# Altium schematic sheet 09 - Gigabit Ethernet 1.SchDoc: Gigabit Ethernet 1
size A3; PageSetup: Record=PageOptions¦CenterHorizontal=True¦CenterVertical=True¦PrintScale=0.70¦XCorrection=1.00¦YCorrection=1.00¦PrintKind=0¦BorderSize=5000000¦LeftOffset=0¦BottomOffset=0¦Orientation=2¦PaperLength=4200¦PaperWidth=2970¦Scale=100¦PaperSource=7¦PrintQuality=600¦MediaType=1¦DitherType=10¦PaperKind=A4¦PrintScaleMode=1; Author: Juan Anzola; SheetNumber: 9; SheetTotal: 20
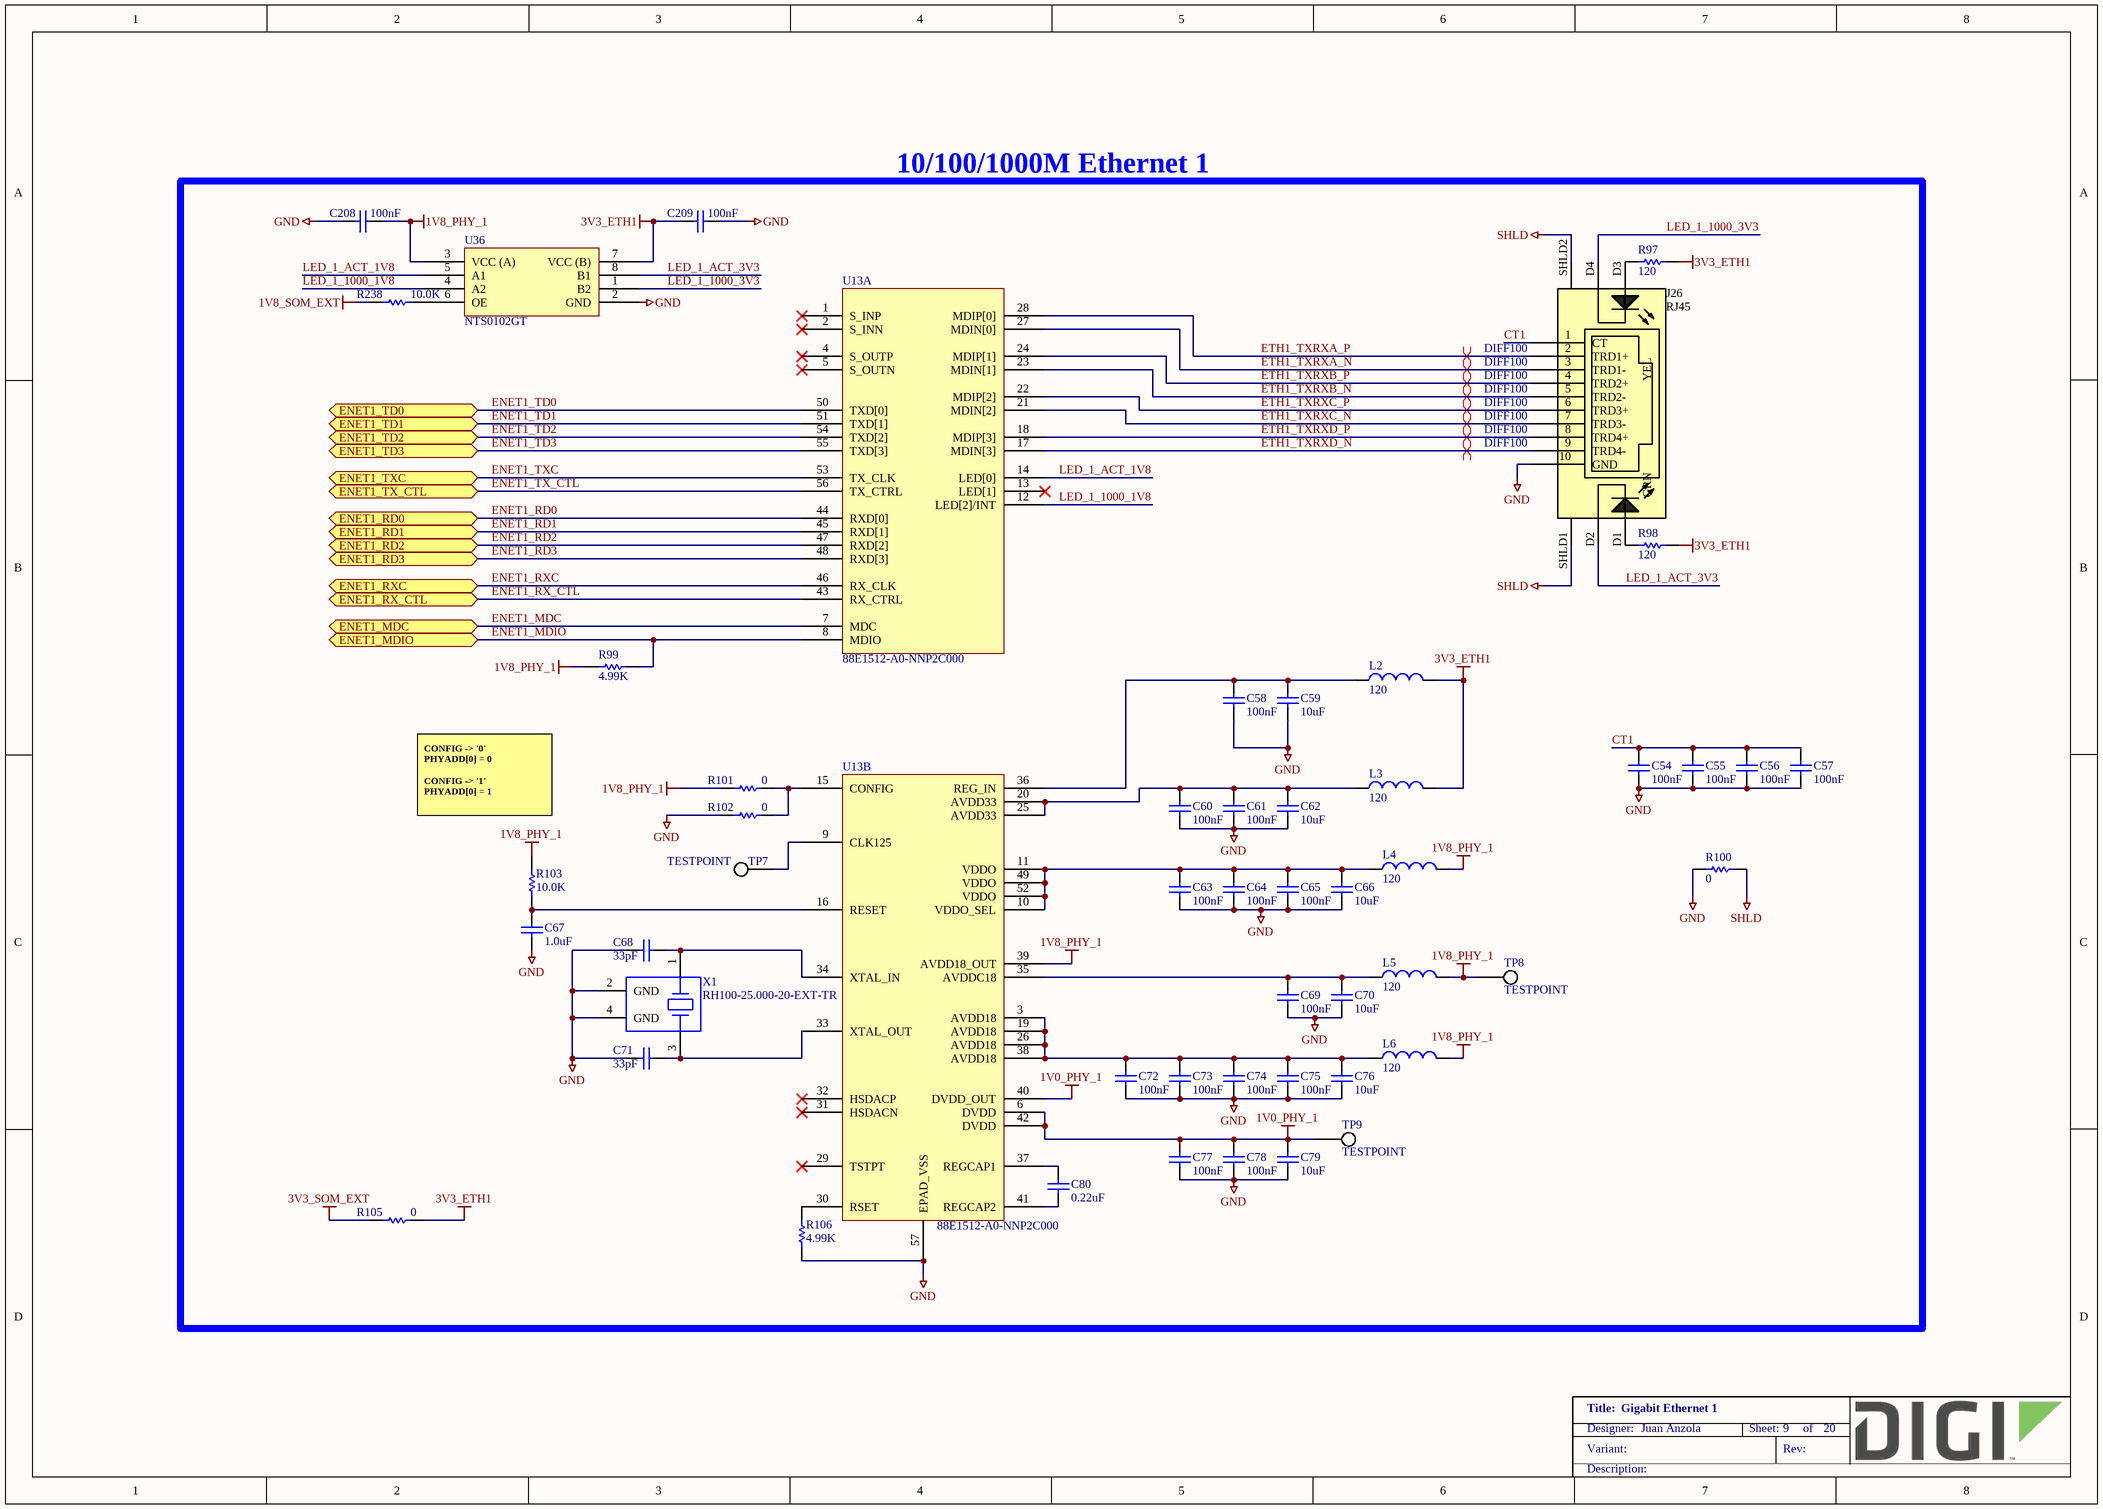
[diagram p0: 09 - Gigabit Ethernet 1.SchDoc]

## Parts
C54  100nF  [CAPC1005X55N]
C55  100nF  [CAPC1005X55N]
C56  100nF  [CAPC1005X55N]
C57  100nF  [CAPC1005X55N]
C58  100nF  [CAPC1005X55N]
C59  10uF  [CAPC2013X135N]
C60  100nF  [CAPC1005X55N]
C61  100nF  [CAPC1005X55N]
C62  10uF  [CAPC2013X135N]
C63  100nF  [CAPC1005X55N]
C64  100nF  [CAPC1005X55N]
C65  100nF  [CAPC1005X55N]
C66  10uF  [CAPC2013X135N]
C67  1.0uF  [CAPC1005X55N]
C68  33pF  [CAPC1005X55N]
C69  100nF  [CAPC1005X55N]
C70  10uF  [CAPC2013X135N]
C71  33pF  [CAPC1005X55N]
C72  100nF  [CAPC1005X55N]
C73  100nF  [CAPC1005X55N]
C74  100nF  [CAPC1005X55N]
C75  100nF  [CAPC1005X55N]
C76  10uF  [CAPC2013X135N]
C77  100nF  [CAPC1005X55N]
C78  100nF  [CAPC1005X55N]
C79  10uF  [CAPC2013X135N]
C80  0.22uF  [CAPC1005X55N]
C208  100nF  [CAPC1005X55N]
C209  100nF  [CAPC1005X55N]
J26  RJ45  [XMULTIPLE_XMG-J1B211]
L2  120  [INDC1005X60N]
L3  120  [INDC1005X60N]
L4  120  [INDC1005X60N]
L5  120  [INDC1005X60N]
L6  120  [INDC1005X60N]
R97  120  [RESC1005X40N]
R98  120  [RESC1005X40N]
R99  4.99K  [RESC1005X40N]
R100  0  [RESC3225X60N]
R101  0  [RESC1609X55N]
R102  0  [RESC1609X55N]
R103  10.0K  [RESC1005X40N]
R105  0  [RESC1609X55N]
R106  4.99K  [RESC1005X40N]
R238  10.0K  [RESC1005X40N]
TP7  TESTPOINT  [TP0762]  (no BOM)
TP8  TESTPOINT  [TP0762]  (no BOM)
TP9  TESTPOINT  [TP0762]  (no BOM)
U13  88E1512-A0-NNP2C000  [QFN56P8mmx8mm-4.50mmPAD]  (parts A,B of 2)
U36  NTS0102GT  [PSON50P195X100X50-8N]
X1  RH100-25.000-20-EXT-TR  [OSC210P320X250X90-4N]

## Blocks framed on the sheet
10/100/1000M Ethernet 1: C54-C80 C208 C209 J26 L2-L6 R97-R103 R105 R106 R238 TP7-TP9 U13 U36 X1

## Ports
ENET1_MDC (bidir), ENET1_MDIO (bidir), ENET1_RD0 (bidir), ENET1_RD1 (bidir), ENET1_RD2 (bidir), ENET1_RD3 (bidir), ENET1_RX_CTL (bidir), ENET1_RXC (bidir), ENET1_TD0 (bidir), ENET1_TD1 (bidir), ENET1_TD2 (bidir), ENET1_TD3 (bidir), ENET1_TX_CTL (bidir), ENET1_TXC (bidir)

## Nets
1V0_PHY_1: C77.2 C78.2 C79.2 TP9.1 U13.6(DVDD) U13.40(DVDD_OUT) U13.42(DVDD)
1V8_PHY_1: C208.2 L4.2 L5.2 L6.2 R99.1 R101.1 R103.2 TP8.1 U13.39(AVDD18_OUT) U36.3(VCC_(A))
1V8_SOM_EXT: R238.1
3V3_ETH1: C209.1 L2.2 L3.2 R97.1 R98.1 R105.2 U36.7(VCC_(B))
3V3_SOM_EXT: R105.1
GND: C54.1 C55.1 C56.1 C57.1 C58.1 C59.1 C60.1 C61.1 C62.1 C63.1 C64.1 C65.1 C66.1 C67.2 C68.1 C69.1 C70.1 C71.1 C72.1 C73.1 C74.1 C75.1 C76.1 C77.1 C78.1 C79.1 C208.1 C209.2 J26.10(GND) R100.1 R102.1 R106.1 U13.57(EPAD_VSS) U36.2(GND) X1.2(GND) X1.4(GND)
SHLD: J26.SHLD1(SHLD) J26.SHLD2(SHLD) R100.2
CT1: C54.2 C55.2 C56.2 C57.2 J26.1(CT)
ENET1_MDC: U13.7(MDC) ; port ENET1_MDC
ENET1_MDIO: R99.2 U13.8(MDIO) ; port ENET1_MDIO
ENET1_RD0: U13.44(RXD[0]) ; port ENET1_RD0
ENET1_RD1: U13.45(RXD[1]) ; port ENET1_RD1
ENET1_RD2: U13.47(RXD[2]) ; port ENET1_RD2
ENET1_RD3: U13.48(RXD[3]) ; port ENET1_RD3
ENET1_RX_CTL: U13.43(RX_CTRL) ; port ENET1_RX_CTL
ENET1_RXC: U13.46(RX_CLK) ; port ENET1_RXC
ENET1_TD0: U13.50(TXD[0]) ; port ENET1_TD0
ENET1_TD1: U13.51(TXD[1]) ; port ENET1_TD1
ENET1_TD2: U13.54(TXD[2]) ; port ENET1_TD2
ENET1_TD3: U13.55(TXD[3]) ; port ENET1_TD3
ENET1_TX_CTL: U13.56(TX_CTRL) ; port ENET1_TX_CTL
ENET1_TXC: U13.53(TX_CLK) ; port ENET1_TXC
ETH1_TXRXA_N: J26.3(TRD1-) U13.27(MDIN[0])
ETH1_TXRXA_P: J26.2(TRD1+) U13.28(MDIP[0])
ETH1_TXRXB_N: J26.5(TRD2-) U13.23(MDIN[1])
ETH1_TXRXB_P: J26.4(TRD2+) U13.24(MDIP[1])
ETH1_TXRXC_N: J26.7(TRD3-) U13.21(MDIN[2])
ETH1_TXRXC_P: J26.6(TRD3+) U13.22(MDIP[2])
ETH1_TXRXD_N: J26.9(TRD4-) U13.17(MDIN[3])
ETH1_TXRXD_P: J26.8(TRD4+) U13.18(MDIP[3])
LED_1_1000_1V8: U13.12(LED[2]/INT) U36.4(A2)
LED_1_1000_3V3: J26.D4 U36.1(B2)
LED_1_ACT_1V8: U13.14(LED[0]) U36.5(A1)
LED_1_ACT_3V3: J26.D2 U36.8(B1)
NetC58_2: C58.2 C59.2 L2.1 U13.36(REG_IN)
NetC60_2: C60.2 C61.2 C62.2 L3.1 U13.20(AVDD33) U13.25(AVDD33)
NetC63_2: C63.2 C64.2 C65.2 C66.2 L4.1 U13.10(VDDO_SEL) U13.11(VDDO) U13.49(VDDO) U13.52(VDDO)
NetC67_1: C67.1 R103.1 U13.16(RESET)
NetC68_2: C68.2 U13.34(XTAL_IN) X1.1
NetC69_2: C69.2 C70.2 L5.1 U13.35(AVDDC18)
NetC71_2: C71.2 U13.33(XTAL_OUT) X1.3
NetC72_2: C72.2 C73.2 C74.2 C75.2 C76.2 L6.1 U13.3(AVDD18) U13.19(AVDD18) U13.26(AVDD18) U13.38(AVDD18)
NetC80_1: C80.1 U13.37(REGCAP1)
NetC80_2: C80.2 U13.41(REGCAP2)
NetJ26_D1: J26.D1 R98.2
NetJ26_D3: J26.D3 R97.2
NetR101_2: R101.2 R102.2 U13.15(CONFIG)
NetR106_2: R106.2 U13.30(RSET)
NetR238_2: R238.2 U36.6(OE)
NetTP7_1: TP7.1 U13.9(CLK125)

Not connected (* = marked no-connect by the designer): U13 1(S_INP)* 2(S_INN)* 4(S_OUTP)* 5(S_OUTN)* 13(LED[1])* 29(TSTPT)* 31(HSDACN)* 32(HSDACP)*

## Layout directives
differential pair; differential pair class DIFF100: ETH1_TXRXA_N, ETH1_TXRXA_P, ETH1_TXRXC_N, ETH1_TXRXC_P, ETH1_TXRXD_N, ETH1_TXRXD_P
differential pair; net class DIFF100; differential pair class DIFF100: ETH1_TXRXB_N, ETH1_TXRXB_P

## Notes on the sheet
- CONFIG -> '0'
  PHYADD[0] = 0
  CONFIG -> '1'
  PHYADD[0] = 1

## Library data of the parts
C54 C56 C57 = 1000006: CAP 100nF 16V 10% X7R 0402; Part_Type: Capacitor; Manufacturer: Murata; Manufacturer_Part_Number: GRM155R71C104KA88D; Digi_PN: 14050552; Component_Life_Cycle_State: CAD Reviewed; Area: 0,95; Project: KITT; Tolerance: 10
C55 C58 C65 C72 C75 C77 C208 C209 = 1000006: CAP 100nF 16V 10% X7R 0402; Part_Type: Capacitor; Manufacturer: Murata; Manufacturer_Part_Number: GRM155R71C104KA88D; Digi_PN: 14050552; Component_Life_Cycle_State: CAD Reviewed; Area: 0,95; Tolerance: 10
C59 C66 C70 C76 C79 = 1000111: CAP CER 10UF 16V 10% X5R 0805; Part_Type: Capacitor; Manufacturer: Murata; Manufacturer_Part_Number: GRM21BR61C106KE15L; Digi_PN: 14050701; Component_Life_Cycle_State: Proven; Area: 3,99; Tolerance: 10
C60 C61 C63 C64 C69 C73 C74 C78 = 1000006: CAP 100nF 16V 10% X7R 0402; Part_Type: Capacitor; Manufacturer: Murata; Manufacturer_Part_Number: GRM155R71C104KA88D; Component_Life_Cycle_State: CAD Reviewed; Area: 0.95; Project: KITT; Tolerance: 10; Digi_PN: 14050552
C62 = 1000111: CAP CER 10UF 16V 10% X5R 0805; Part_Type: Capacitor; Manufacturer: Murata; Manufacturer_Part_Number: GRM21BR61C106KE15L; Digi_PN: 14050701; Component_Life_Cycle_State: Proven; Area: 3.99; Project: Adjustable Foundation; Tolerance: 10
C67 = 1001167: CAP CER 1UF 10V 10% X5R 0402
C68 C71 = 1002646: CAP CER 33PF 50V C0G/NP0 0402; Part_Type: Capacitor; Manufacturer: Murata; Manufacturer_Part_Number: GCM1555C1H330JA16D; Digi_PN: 14050400; Component_Life_Cycle_State: Reviewed; Area: 2,12; Voltage: 50; Tolerance: 5%
C80 = 1001883: CAP CER 0.22UF 6.3V X7R 0402; Part_Type: Capacitor; Manufacturer: Taiyo Yuden; Manufacturer_Part_Number: JMK105B7224KV-F; Digi_PN: 14000067; Component_Life_Cycle_State: Reviewed; Area: 2.2; Project: Powerley Energy Bridge; Tolerance: 10%
J26 = 1002612: CONN MAGJACK 1PORT 1000 BASE-T IND; Part_Type: Connector; Manufacturer: XMultiple; Manufacturer_Part_Number: XMG-J1B2211NPA-1-DIG; Digi_PN: 18000772; Component_Life_Cycle_State: Created; Area: 339.5; Project: DIGI CC8X SOM
L2-L6 = 1001175: FERRITE BEAD 120 OHM .35A 0402; Part_Type: Filter; Manufacturer: Wurth Electronics Inc; Manufacturer_Part_Number: 7427927112; Digi_PN: 21000128; Component_Life_Cycle_State: Reviewed; Area: 1,12
R97 R98 = 1001158: RES 120 OHM 1/16W 1% 0402 SMD; Part_Type: Resistor; Manufacturer: Yageo; Manufacturer_Part_Number: RC0402FR-07120RL; Digi_PN: 13050832; Component_Life_Cycle_State: Reviewed; Area: 0.95; Project: CCWMX6_SBC board; Note: 13051102 = Digi No. for GE WDNU
R99 R106 = 1000474: RES 4.99K OHM 1/10W 1% 0402 SMD; Part_Type: Resistor; Manufacturer: Panasonic - ECG; Manufacturer_Part_Number: ERJ-2RKF4991X; Digi_PN: 13050860; Component_Life_Cycle_State: CAD Reviewed; Area: 0,95; Power_WV_SRF: 100
R100 = 1000229: RES 0.0 OHM 1/2W 1210 SMD; Part_Type: Resistor; Manufacturer: Vishay Dale; Manufacturer_Part_Number: CRCW12100000Z0EA; Digi_PN: 13050962; Component_Life_Cycle_State: Proven; Area: 11,07
R101 R102 R105 = 1000208: RES 0.0 OHM 1/10W 0603; Part_Type: Resistor; Manufacturer: Panasonic - ECG; Manufacturer_Part_Number: ERJ-3GEY0R00V; Note: 13051103 = Digi No. for GE WDNU; Digi_PN: 13050568; Component_Life_Cycle_State: Reviewed; Area: 2,5; Voltage: 75V
R103 = 1000537: RES 10.0K OHM 1/10W 1% 0402 SMD
R238 = 1000537: RES 10.0K OHM 1/10W 1% 0402 SMD; Part_Type: Resistor; Manufacturer: Panasonic - ECG; Manufacturer_Part_Number: ERJ-2RKF1002X; Digi_PN: 13051084; Component_Life_Cycle_State: CAD Reviewed; Area: 0,95; Power_WV_SRF: 100
TP7-TP9 = CAD0011: TEST POINT 30MIL PAD SMT; Component_Life_Cycle_State: Reviewed; Area: 0,58; Project: CLC
U13 = 1002866: SMIC,Gb Eth phy 0/70°C QFN-56 8x8mm; Part_Type: IC; Manufacturer: Marvell; Digi_PN: ACC-240174; Component_Life_Cycle_State: Created; Area: 64
U36 = 1002597: IC TRANSLATING TXRX 8XSON; Manufacturer: NXP Semiconductors; Manufacturer_Part_Number: NTS0102GT,115; Digi_PN: 16000138; Component_Life_Cycle_State: Reviewed; Area: 3,9
X1 = 1001497: SMCRY,25MHZ 50PPM 20PF RH100 EXT; Part_Type: Crystals-Oscillators; Manufacturer: Raltron; Digi_PN: 20000285; Component_Life_Cycle_State: Reviewed; Area: 3,2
